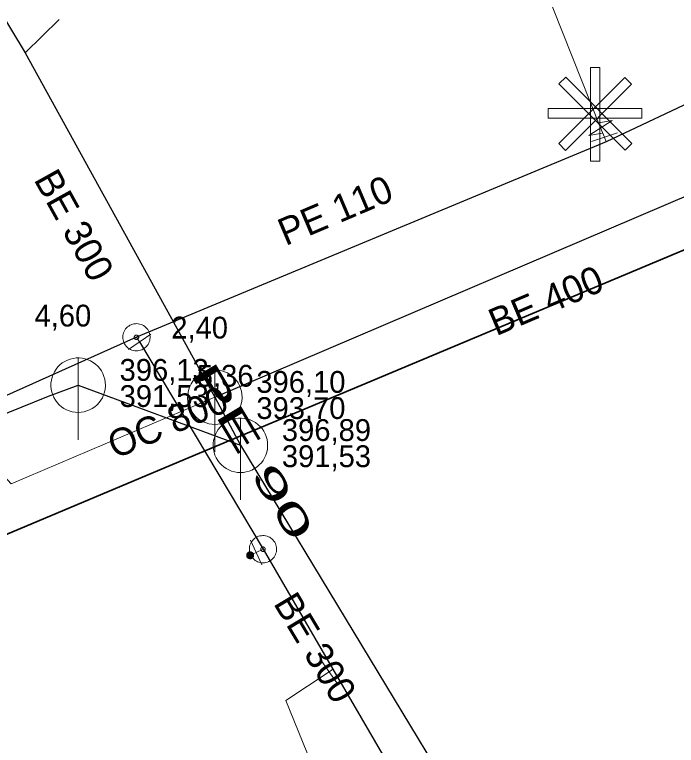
# Model space of a CAD drawing. Extents: x -809028 to -807737, y -990545 to -989489.
# Drawn here: x -808576.58 to -808552.29, y -989992.11 to -989965.3 of the extents above; entities that cross this region are included whole.
import ezdxf

# ---------------------------------------------------------------- set-up
doc = ezdxf.new("R2010")
doc.units = 0
doc.header["$LTSCALE"] = 0.32
for name, color, linetype, lineweight in [('1', 7, 'Continuous', 13), ('11', 7, 'Continuous', 13), ('12', 7, 'Continuous', 13), ('13', 7, 'Continuous', 13), ('14', 7, 'Continuous', 25), ('17', 7, 'Continuous', 25), ('22', 7, 'Continuous', 13), ('34', 7, 'Continuous', 13), ('47', 7, 'Continuous', 13), ('9', 7, 'Continuous', 13)]:
    doc.layers.add(name, color=color, linetype=linetype, lineweight=lineweight)

msp = doc.modelspace()

# ---------------------------------------------------------------- linework, layer by layer
at = {"layer": '11'}
msp.add_line((-808574.951, -989965.476), (-808576.188, -989966.702), dxfattribs=at)
msp.add_lwpolyline([(-808584.044, -989974.464), (-808576.71, -989982.519), (-808569.23, -989979.334)], dxfattribs=at)
at = {"layer": '12'}
for points in [[(-808555.447, -989967.24), (-808555.097, -989967.24), (-808555.097, -989970.675), (-808555.447, -989970.675)], [(-808554.181, -989967.604), (-808553.933, -989967.852), (-808556.362, -989970.281), (-808556.608, -989970.033)], [(-808556.6, -989967.843), (-808556.353, -989967.595), (-808553.924, -989970.024), (-808554.171, -989970.272)], [(-808553.563, -989968.749), (-808553.563, -989969.099), (-808556.998, -989969.099), (-808556.998, -989968.749)]]:
    msp.add_lwpolyline(points, close=True, dxfattribs=at)
at = {"layer": '13'}
for points in [[(-808554.927, -989969.793), (-808555.077, -989969.458), (-808560.651, -989955.405)], [(-808565.037, -989989.409), (-808566.625, -989990.465), (-808565.535, -989993.138), (-808569.495, -989996.061)]]:
    msp.add_lwpolyline(points, dxfattribs=at)
at = {"layer": '14', "lineweight": 13}
for p, q in [((-808554.87, -989969.971), (-808554.927, -989969.793)), ((-808572.108, -989977.136), (-808571.991, -989977.309)), ((-808567.716, -989985.034), (-808567.935, -989985.135)), ((-808567.463, -989984.912), (-808567.716, -989985.034))]:
    msp.add_line(p, q, dxfattribs=at)
at = {"layer": '14'}
msp.add_line((-808574.249, -989978.893), (-808568.292, -989981.1), dxfattribs=at)
for points in [[(-808584.261, -989952.94), (-808577.742, -989964.137), (-808576.188, -989966.702), (-808569.23, -989979.334)], [(-808569.23, -989979.334), (-808549.572, -989970.943), (-808544.651, -989968.803)], [(-808603.873, -989990.789), (-808591.761, -989985.934), (-808575.342, -989979.291), (-808574.249, -989978.893)], [(-808569.23, -989979.334), (-808568.292, -989981.1), (-808559.407, -989995.771), (-808556.033, -990001.675), (-808538.055, -990031.421), (-808535.03, -990036.115), (-808522.248, -990056.603), (-808501.469, -990070.893)]]:
    msp.add_lwpolyline(points, dxfattribs=at)
at = {"layer": '14', "lineweight": 13}
msp.add_lwpolyline([(-808565.037, -989989.409), (-808564.997, -989989.381), (-808564.903, -989989.315)], dxfattribs=at)
at = {"layer": '17'}
msp.add_line((-808571.991, -989977.309), (-808567.463, -989984.912), dxfattribs=at)
for points in [[(-808533.093, -989960.754), (-808533.43, -989961.315), (-808534.199, -989961.752), (-808534.647, -989961.113), (-808551.155, -989968.217), (-808554.87, -989969.971), (-808572.108, -989977.136)], [(-808572.108, -989977.136), (-808579.511, -989980.449), (-808588.848, -989984.113), (-808599.937, -989988.868)], [(-808567.463, -989984.912), (-808564.903, -989989.315), (-808559.226, -989999.059), (-808546.874, -990020.305), (-808545.364, -990022.763), (-808542.872, -990026.881), (-808542.522, -990027.583), (-808541.645, -990028.908), (-808532.624, -990043.916), (-808522.756, -990058.613), (-808516.815, -990065.144), (-808508.914, -990069.898)]]:
    msp.add_lwpolyline(points, dxfattribs=at)
at = {"layer": '17', "lineweight": 35}
msp.add_lwpolyline([(-808620.873, -990007.571), (-808617.482, -990003.458), (-808605.335, -989996.355), (-808589.077, -989989.493), (-808570.179, -989981.543), (-808534.115, -989966.436)], dxfattribs=at)
at = {"layer": '22'}
for p, q in [((-808574.249, -989980.893), (-808574.248, -989977.893)), ((-808569.23, -989981.334), (-808569.229, -989978.334)), ((-808568.292, -989983.1), (-808568.291, -989980.1))]:
    msp.add_line(p, q, dxfattribs=at)
for points in [[(-808573.249, -989978.893), (-808573.254, -989978.784), (-808573.272, -989978.676), (-808573.302, -989978.57), (-808573.342, -989978.469), (-808573.394, -989978.372), (-808573.456, -989978.282), (-808573.528, -989978.199), (-808573.608, -989978.125), (-808573.696, -989978.059), (-808573.79, -989978.004), (-808573.89, -989977.959), (-808573.995, -989977.926), (-808574.102, -989977.904), (-808574.211, -989977.894), (-808574.321, -989977.896), (-808574.429, -989977.91), (-808574.536, -989977.935), (-808574.639, -989977.972), (-808574.737, -989978.021), (-808574.829, -989978.079), (-808574.915, -989978.148), (-808574.992, -989978.225), (-808575.061, -989978.311), (-808575.12, -989978.403), (-808575.168, -989978.501), (-808575.205, -989978.604), (-808575.231, -989978.711), (-808575.245, -989978.819), (-808575.248, -989978.929), (-808575.238, -989979.038), (-808575.217, -989979.145), (-808575.183, -989979.249), (-808575.139, -989979.349), (-808575.084, -989979.444), (-808575.018, -989979.532), (-808574.944, -989979.612), (-808574.861, -989979.684), (-808574.771, -989979.746), (-808574.675, -989979.798), (-808574.573, -989979.839), (-808574.468, -989979.869), (-808574.36, -989979.887), (-808574.25, -989979.893), (-808574.141, -989979.887), (-808574.033, -989979.869), (-808573.928, -989979.84), (-808573.826, -989979.799), (-808573.729, -989979.747), (-808573.639, -989979.685), (-808573.556, -989979.614), (-808573.481, -989979.534), (-808573.416, -989979.446), (-808573.36, -989979.352), (-808573.316, -989979.252), (-808573.282, -989979.148), (-808573.26, -989979.04), (-808573.25, -989978.931)], [(-808568.23, -989979.334), (-808568.235, -989979.225), (-808568.253, -989979.117), (-808568.283, -989979.011), (-808568.323, -989978.91), (-808568.375, -989978.813), (-808568.437, -989978.723), (-808568.509, -989978.64), (-808568.589, -989978.566), (-808568.677, -989978.5), (-808568.771, -989978.445), (-808568.871, -989978.4), (-808568.976, -989978.367), (-808569.083, -989978.345), (-808569.192, -989978.335), (-808569.302, -989978.337), (-808569.41, -989978.351), (-808569.517, -989978.376), (-808569.62, -989978.413), (-808569.718, -989978.462), (-808569.81, -989978.52), (-808569.896, -989978.589), (-808569.973, -989978.666), (-808570.042, -989978.752), (-808570.101, -989978.844), (-808570.149, -989978.942), (-808570.186, -989979.045), (-808570.212, -989979.152), (-808570.226, -989979.26), (-808570.229, -989979.37), (-808570.219, -989979.479), (-808570.198, -989979.586), (-808570.164, -989979.69), (-808570.12, -989979.79), (-808570.065, -989979.885), (-808569.999, -989979.973), (-808569.925, -989980.053), (-808569.842, -989980.125), (-808569.752, -989980.187), (-808569.656, -989980.239), (-808569.554, -989980.28), (-808569.449, -989980.31), (-808569.341, -989980.328), (-808569.231, -989980.334), (-808569.122, -989980.328), (-808569.014, -989980.31), (-808568.909, -989980.281), (-808568.807, -989980.24), (-808568.71, -989980.188), (-808568.62, -989980.126), (-808568.537, -989980.055), (-808568.462, -989979.975), (-808568.397, -989979.887), (-808568.341, -989979.793), (-808568.297, -989979.693), (-808568.263, -989979.589), (-808568.241, -989979.481), (-808568.231, -989979.372)], [(-808567.292, -989981.1), (-808567.297, -989980.991), (-808567.315, -989980.883), (-808567.345, -989980.777), (-808567.385, -989980.676), (-808567.437, -989980.579), (-808567.499, -989980.489), (-808567.571, -989980.406), (-808567.651, -989980.332), (-808567.739, -989980.266), (-808567.833, -989980.211), (-808567.933, -989980.166), (-808568.038, -989980.133), (-808568.145, -989980.111), (-808568.254, -989980.101), (-808568.364, -989980.103), (-808568.472, -989980.117), (-808568.579, -989980.142), (-808568.682, -989980.179), (-808568.78, -989980.228), (-808568.872, -989980.286), (-808568.958, -989980.355), (-808569.035, -989980.432), (-808569.104, -989980.518), (-808569.163, -989980.61), (-808569.211, -989980.708), (-808569.248, -989980.811), (-808569.274, -989980.918), (-808569.288, -989981.026), (-808569.291, -989981.136), (-808569.281, -989981.245), (-808569.26, -989981.352), (-808569.226, -989981.456), (-808569.182, -989981.556), (-808569.127, -989981.651), (-808569.061, -989981.739), (-808568.987, -989981.819), (-808568.904, -989981.891), (-808568.814, -989981.953), (-808568.718, -989982.005), (-808568.616, -989982.046), (-808568.511, -989982.076), (-808568.403, -989982.094), (-808568.293, -989982.1), (-808568.184, -989982.094), (-808568.076, -989982.076), (-808567.971, -989982.047), (-808567.869, -989982.006), (-808567.772, -989981.954), (-808567.682, -989981.892), (-808567.599, -989981.821), (-808567.524, -989981.741), (-808567.459, -989981.653), (-808567.403, -989981.559), (-808567.359, -989981.459), (-808567.325, -989981.355), (-808567.303, -989981.247), (-808567.293, -989981.138)]]:
    msp.add_lwpolyline(points, close=True, dxfattribs=at)
at = {"layer": '34'}
for p, q in [((-808554.452, -989969.636), (-808555.402, -989969.948)), ((-808571.577, -989977.027), (-808572.404, -989977.589)), ((-808567.926, -989984.58), (-808567.506, -989985.488)), ((-808565.322, -989988.998), (-808564.752, -989989.819))]:
    msp.add_line(p, q, dxfattribs=at)
at = {"layer": '47'}
msp.add_line((-808554.648, -989969.182), (-808555.151, -989969.271), dxfattribs=at)
msp.add_lwpolyline([(-808554.648, -989969.182), (-808555.505, -989969.733), (-808555.002, -989969.644)], dxfattribs=at)
for points in [[(-808571.646, -989976.944), (-808571.669, -989976.897), (-808571.696, -989976.852), (-808571.728, -989976.811), (-808571.763, -989976.773), (-808571.804, -989976.738), (-808571.847, -989976.709), (-808571.893, -989976.685), (-808571.941, -989976.665), (-808571.991, -989976.65), (-808572.043, -989976.64), (-808572.095, -989976.636), (-808572.148, -989976.638), (-808572.199, -989976.644), (-808572.25, -989976.657), (-808572.299, -989976.674), (-808572.346, -989976.697), (-808572.391, -989976.724), (-808572.433, -989976.756), (-808572.47, -989976.791), (-808572.505, -989976.832), (-808572.534, -989976.875), (-808572.559, -989976.922), (-808572.579, -989976.97), (-808572.594, -989977.019), (-808572.603, -989977.071), (-808572.607, -989977.123), (-808572.606, -989977.176), (-808572.599, -989977.227), (-808572.586, -989977.278), (-808572.569, -989977.327), (-808572.546, -989977.374), (-808572.519, -989977.419), (-808572.488, -989977.461), (-808572.452, -989977.498), (-808572.411, -989977.533), (-808572.369, -989977.562), (-808572.322, -989977.588), (-808572.274, -989977.608), (-808572.224, -989977.622), (-808572.172, -989977.631), (-808572.12, -989977.635), (-808572.068, -989977.635), (-808572.016, -989977.627), (-808571.965, -989977.614), (-808571.916, -989977.597), (-808571.869, -989977.574), (-808571.824, -989977.547), (-808571.783, -989977.516), (-808571.745, -989977.48), (-808571.71, -989977.439), (-808571.681, -989977.397), (-808571.656, -989977.351), (-808571.636, -989977.302), (-808571.622, -989977.252), (-808571.612, -989977.2), (-808571.608, -989977.148), (-808571.609, -989977.096), (-808571.616, -989977.044), (-808571.629, -989976.993)], [(-808572.032, -989977.104), (-808572.035, -989977.096), (-808572.04, -989977.089), (-808572.045, -989977.082), (-808572.051, -989977.076), (-808572.058, -989977.07), (-808572.065, -989977.066), (-808572.072, -989977.061), (-808572.08, -989977.058), (-808572.089, -989977.056), (-808572.097, -989977.054), (-808572.106, -989977.054), (-808572.114, -989977.054), (-808572.123, -989977.055), (-808572.131, -989977.056), (-808572.139, -989977.06), (-808572.147, -989977.063), (-808572.154, -989977.068), (-808572.161, -989977.073), (-808572.167, -989977.079), (-808572.173, -989977.086), (-808572.177, -989977.093), (-808572.182, -989977.1), (-808572.185, -989977.108), (-808572.188, -989977.117), (-808572.189, -989977.125), (-808572.189, -989977.134), (-808572.189, -989977.142), (-808572.188, -989977.151), (-808572.187, -989977.159), (-808572.183, -989977.167), (-808572.18, -989977.175), (-808572.175, -989977.182), (-808572.17, -989977.189), (-808572.164, -989977.195), (-808572.157, -989977.201), (-808572.151, -989977.206), (-808572.143, -989977.21), (-808572.135, -989977.213), (-808572.126, -989977.216), (-808572.118, -989977.217), (-808572.109, -989977.217), (-808572.101, -989977.217), (-808572.092, -989977.216), (-808572.084, -989977.215), (-808572.076, -989977.211), (-808572.068, -989977.208), (-808572.061, -989977.203), (-808572.054, -989977.198), (-808572.048, -989977.192), (-808572.042, -989977.185), (-808572.037, -989977.179), (-808572.033, -989977.171), (-808572.03, -989977.163), (-808572.028, -989977.154), (-808572.026, -989977.146), (-808572.026, -989977.137), (-808572.026, -989977.129), (-808572.027, -989977.12), (-808572.028, -989977.112)], [(-808567.207, -989985.341), (-808567.164, -989985.312), (-808567.123, -989985.278), (-808567.087, -989985.241), (-808567.054, -989985.2), (-808567.026, -989985.156), (-808567.003, -989985.108), (-808566.986, -989985.059), (-808566.973, -989985.009), (-808566.965, -989984.957), (-808566.963, -989984.905), (-808566.966, -989984.852), (-808566.976, -989984.801), (-808566.989, -989984.751), (-808567.009, -989984.702), (-808567.033, -989984.656), (-808567.062, -989984.613), (-808567.096, -989984.572), (-808567.134, -989984.535), (-808567.174, -989984.503), (-808567.218, -989984.475), (-808567.266, -989984.452), (-808567.315, -989984.434), (-808567.366, -989984.421), (-808567.417, -989984.413), (-808567.469, -989984.412), (-808567.522, -989984.415), (-808567.574, -989984.424), (-808567.623, -989984.438), (-808567.672, -989984.458), (-808567.718, -989984.482), (-808567.761, -989984.511), (-808567.802, -989984.545), (-808567.839, -989984.582), (-808567.871, -989984.623), (-808567.899, -989984.667), (-808567.922, -989984.714), (-808567.941, -989984.763), (-808567.954, -989984.814), (-808567.961, -989984.866), (-808567.962, -989984.918), (-808567.959, -989984.971), (-808567.951, -989985.022), (-808567.936, -989985.072), (-808567.916, -989985.121), (-808567.892, -989985.167), (-808567.863, -989985.21), (-808567.829, -989985.251), (-808567.793, -989985.287), (-808567.751, -989985.32), (-808567.707, -989985.348), (-808567.66, -989985.371), (-808567.611, -989985.389), (-808567.56, -989985.402), (-808567.508, -989985.409), (-808567.456, -989985.411), (-808567.403, -989985.408), (-808567.353, -989985.399), (-808567.302, -989985.385), (-808567.253, -989985.365)], [(-808567.421, -989984.982), (-808567.413, -989984.977), (-808567.407, -989984.972), (-808567.401, -989984.966), (-808567.396, -989984.959), (-808567.391, -989984.952), (-808567.387, -989984.944), (-808567.384, -989984.936), (-808567.382, -989984.928), (-808567.381, -989984.919), (-808567.381, -989984.91), (-808567.381, -989984.901), (-808567.383, -989984.893), (-808567.385, -989984.885), (-808567.387, -989984.877), (-808567.392, -989984.87), (-808567.397, -989984.862), (-808567.402, -989984.856), (-808567.408, -989984.85), (-808567.415, -989984.845), (-808567.422, -989984.84), (-808567.43, -989984.836), (-808567.438, -989984.833), (-808567.446, -989984.831), (-808567.456, -989984.829), (-808567.464, -989984.83), (-808567.473, -989984.83), (-808567.481, -989984.832), (-808567.489, -989984.834), (-808567.497, -989984.836), (-808567.504, -989984.841), (-808567.512, -989984.846), (-808567.518, -989984.851), (-808567.524, -989984.857), (-808567.529, -989984.864), (-808567.534, -989984.871), (-808567.538, -989984.878), (-808567.541, -989984.887), (-808567.543, -989984.895), (-808567.545, -989984.905), (-808567.544, -989984.913), (-808567.544, -989984.922), (-808567.542, -989984.93), (-808567.54, -989984.938), (-808567.538, -989984.946), (-808567.533, -989984.953), (-808567.528, -989984.961), (-808567.523, -989984.967), (-808567.517, -989984.973), (-808567.51, -989984.978), (-808567.503, -989984.983), (-808567.496, -989984.987), (-808567.487, -989984.99), (-808567.479, -989984.992), (-808567.47, -989984.993), (-808567.461, -989984.993), (-808567.452, -989984.993), (-808567.444, -989984.991), (-808567.436, -989984.989), (-808567.428, -989984.987)]]:
    msp.add_lwpolyline(points, close=True, dxfattribs=at)
at = {"layer": '9'}
for points in [[(-808568.061, -989985.135), (-808568.061, -989985.148), (-808568.059, -989985.161), (-808568.056, -989985.174), (-808568.051, -989985.186), (-808568.045, -989985.198), (-808568.038, -989985.209), (-808568.03, -989985.219), (-808568.02, -989985.229), (-808568.01, -989985.237), (-808567.999, -989985.244), (-808567.987, -989985.25), (-808567.975, -989985.255), (-808567.962, -989985.258), (-808567.949, -989985.26), (-808567.936, -989985.262), (-808567.923, -989985.261), (-808567.91, -989985.259), (-808567.897, -989985.256), (-808567.885, -989985.251), (-808567.873, -989985.245), (-808567.862, -989985.238), (-808567.852, -989985.23), (-808567.842, -989985.22), (-808567.834, -989985.21), (-808567.827, -989985.199), (-808567.821, -989985.187), (-808567.816, -989985.175), (-808567.813, -989985.162), (-808567.811, -989985.149), (-808567.809, -989985.136), (-808567.81, -989985.123), (-808567.812, -989985.11), (-808567.815, -989985.097), (-808567.82, -989985.085), (-808567.826, -989985.073), (-808567.833, -989985.062), (-808567.841, -989985.052), (-808567.851, -989985.042), (-808567.861, -989985.034), (-808567.872, -989985.027), (-808567.884, -989985.021), (-808567.896, -989985.016), (-808567.909, -989985.013), (-808567.922, -989985.011), (-808567.935, -989985.01), (-808567.948, -989985.01), (-808567.961, -989985.012), (-808567.974, -989985.015), (-808567.986, -989985.02), (-808567.998, -989985.026), (-808568.009, -989985.033), (-808568.019, -989985.041), (-808568.029, -989985.051), (-808568.037, -989985.061), (-808568.044, -989985.072), (-808568.05, -989985.084), (-808568.055, -989985.096), (-808568.058, -989985.109), (-808568.06, -989985.122)], [(-808568.041, -989985.135), (-808568.042, -989985.146), (-808568.04, -989985.157), (-808568.037, -989985.168), (-808568.033, -989985.178), (-808568.028, -989985.188), (-808568.022, -989985.197), (-808568.015, -989985.206), (-808568.007, -989985.214), (-808567.998, -989985.221), (-808567.989, -989985.227), (-808567.979, -989985.232), (-808567.969, -989985.236), (-808567.958, -989985.239), (-808567.947, -989985.242), (-808567.936, -989985.242), (-808567.925, -989985.242), (-808567.914, -989985.24), (-808567.903, -989985.237), (-808567.893, -989985.233), (-808567.883, -989985.228), (-808567.874, -989985.222), (-808567.865, -989985.215), (-808567.857, -989985.207), (-808567.85, -989985.198), (-808567.844, -989985.189), (-808567.839, -989985.179), (-808567.835, -989985.169), (-808567.832, -989985.158), (-808567.83, -989985.147), (-808567.829, -989985.136), (-808567.829, -989985.125), (-808567.831, -989985.114), (-808567.834, -989985.103), (-808567.838, -989985.093), (-808567.843, -989985.083), (-808567.849, -989985.074), (-808567.856, -989985.065), (-808567.864, -989985.057), (-808567.873, -989985.05), (-808567.882, -989985.044), (-808567.892, -989985.039), (-808567.902, -989985.035), (-808567.913, -989985.032), (-808567.924, -989985.03), (-808567.935, -989985.03), (-808567.946, -989985.029), (-808567.957, -989985.031), (-808567.968, -989985.034), (-808567.978, -989985.038), (-808567.988, -989985.043), (-808567.997, -989985.049), (-808568.006, -989985.056), (-808568.014, -989985.064), (-808568.021, -989985.073), (-808568.027, -989985.082), (-808568.032, -989985.092), (-808568.036, -989985.102), (-808568.039, -989985.113), (-808568.041, -989985.124)], [(-808568.022, -989985.135), (-808568.022, -989985.144), (-808568.021, -989985.153), (-808568.018, -989985.162), (-808568.015, -989985.17), (-808568.011, -989985.178), (-808568.006, -989985.186), (-808568, -989985.193), (-808567.994, -989985.199), (-808567.987, -989985.205), (-808567.979, -989985.21), (-808567.971, -989985.214), (-808567.963, -989985.217), (-808567.954, -989985.22), (-808567.945, -989985.221), (-808567.936, -989985.223), (-808567.927, -989985.222), (-808567.918, -989985.221), (-808567.909, -989985.218), (-808567.901, -989985.215), (-808567.893, -989985.211), (-808567.885, -989985.206), (-808567.878, -989985.2), (-808567.872, -989985.194), (-808567.866, -989985.187), (-808567.861, -989985.179), (-808567.857, -989985.171), (-808567.854, -989985.163), (-808567.851, -989985.154), (-808567.85, -989985.145), (-808567.848, -989985.136), (-808567.849, -989985.127), (-808567.85, -989985.118), (-808567.853, -989985.109), (-808567.856, -989985.101), (-808567.86, -989985.093), (-808567.865, -989985.085), (-808567.871, -989985.078), (-808567.877, -989985.072), (-808567.884, -989985.066), (-808567.892, -989985.061), (-808567.9, -989985.057), (-808567.908, -989985.054), (-808567.917, -989985.051), (-808567.926, -989985.05), (-808567.935, -989985.049), (-808567.944, -989985.049), (-808567.953, -989985.05), (-808567.962, -989985.053), (-808567.97, -989985.056), (-808567.978, -989985.06), (-808567.986, -989985.065), (-808567.993, -989985.071), (-808567.999, -989985.077), (-808568.005, -989985.084), (-808568.01, -989985.092), (-808568.014, -989985.1), (-808568.017, -989985.108), (-808568.02, -989985.117), (-808568.021, -989985.126)], [(-808568.002, -989985.135), (-808568.002, -989985.142), (-808568.001, -989985.149), (-808568, -989985.156), (-808567.997, -989985.162), (-808567.994, -989985.168), (-808567.99, -989985.174), (-808567.986, -989985.18), (-808567.981, -989985.185), (-808567.975, -989985.189), (-808567.969, -989985.193), (-808567.963, -989985.196), (-808567.957, -989985.199), (-808567.95, -989985.2), (-808567.943, -989985.203), (-808567.936, -989985.203), (-808567.929, -989985.203), (-808567.922, -989985.201), (-808567.915, -989985.2), (-808567.909, -989985.197), (-808567.902, -989985.194), (-808567.897, -989985.19), (-808567.891, -989985.186), (-808567.886, -989985.181), (-808567.882, -989985.175), (-808567.878, -989985.169), (-808567.875, -989985.163), (-808567.872, -989985.157), (-808567.87, -989985.15), (-808567.869, -989985.143), (-808567.868, -989985.136), (-808567.868, -989985.129), (-808567.869, -989985.122), (-808567.871, -989985.115), (-808567.874, -989985.109), (-808567.877, -989985.102), (-808567.881, -989985.097), (-808567.885, -989985.091), (-808567.89, -989985.086), (-808567.896, -989985.082), (-808567.901, -989985.078), (-808567.908, -989985.075), (-808567.914, -989985.072), (-808567.921, -989985.07), (-808567.928, -989985.069), (-808567.935, -989985.069), (-808567.942, -989985.069), (-808567.949, -989985.069), (-808567.956, -989985.071), (-808567.962, -989985.074), (-808567.968, -989985.077), (-808567.974, -989985.081), (-808567.98, -989985.085), (-808567.985, -989985.09), (-808567.989, -989985.096), (-808567.993, -989985.101), (-808567.996, -989985.108), (-808567.999, -989985.114), (-808568, -989985.121), (-808568.002, -989985.128)], [(-808567.982, -989985.135), (-808567.982, -989985.14), (-808567.982, -989985.145), (-808567.981, -989985.15), (-808567.979, -989985.154), (-808567.977, -989985.159), (-808567.974, -989985.163), (-808567.971, -989985.166), (-808567.967, -989985.17), (-808567.964, -989985.173), (-808567.96, -989985.176), (-808567.955, -989985.178), (-808567.951, -989985.18), (-808567.946, -989985.181), (-808567.941, -989985.183), (-808567.936, -989985.183), (-808567.931, -989985.183), (-808567.926, -989985.182), (-808567.921, -989985.181), (-808567.917, -989985.179), (-808567.912, -989985.177), (-808567.908, -989985.174), (-808567.904, -989985.171), (-808567.901, -989985.167), (-808567.898, -989985.164), (-808567.895, -989985.16), (-808567.893, -989985.155), (-808567.891, -989985.151), (-808567.89, -989985.146), (-808567.889, -989985.141), (-808567.888, -989985.136), (-808567.888, -989985.131), (-808567.889, -989985.126), (-808567.89, -989985.121), (-808567.892, -989985.117), (-808567.894, -989985.112), (-808567.897, -989985.108), (-808567.9, -989985.104), (-808567.903, -989985.101), (-808567.907, -989985.098), (-808567.911, -989985.095), (-808567.916, -989985.093), (-808567.92, -989985.091), (-808567.925, -989985.09), (-808567.93, -989985.089), (-808567.935, -989985.089), (-808567.94, -989985.089), (-808567.945, -989985.09), (-808567.95, -989985.09), (-808567.954, -989985.092), (-808567.959, -989985.094), (-808567.963, -989985.097), (-808567.966, -989985.1), (-808567.97, -989985.103), (-808567.973, -989985.107), (-808567.976, -989985.111), (-808567.978, -989985.116), (-808567.98, -989985.12), (-808567.981, -989985.125), (-808567.982, -989985.13)], [(-808567.962, -989985.135), (-808567.962, -989985.138), (-808567.963, -989985.141), (-808567.962, -989985.143), (-808567.961, -989985.146), (-808567.96, -989985.149), (-808567.958, -989985.151), (-808567.956, -989985.153), (-808567.954, -989985.155), (-808567.952, -989985.157), (-808567.95, -989985.159), (-808567.947, -989985.161), (-808567.944, -989985.162), (-808567.942, -989985.162), (-808567.939, -989985.163), (-808567.936, -989985.163), (-808567.933, -989985.163), (-808567.93, -989985.163), (-808567.927, -989985.162), (-808567.925, -989985.161), (-808567.922, -989985.16), (-808567.92, -989985.158), (-808567.917, -989985.156), (-808567.915, -989985.154), (-808567.914, -989985.152), (-808567.912, -989985.15), (-808567.911, -989985.147), (-808567.909, -989985.144), (-808567.909, -989985.142), (-808567.908, -989985.139), (-808567.907, -989985.136), (-808567.908, -989985.133), (-808567.908, -989985.13), (-808567.909, -989985.127), (-808567.91, -989985.125), (-808567.911, -989985.122), (-808567.913, -989985.12), (-808567.914, -989985.117), (-808567.916, -989985.115), (-808567.919, -989985.114), (-808567.921, -989985.112), (-808567.924, -989985.111), (-808567.926, -989985.11), (-808567.929, -989985.109), (-808567.932, -989985.109), (-808567.935, -989985.108), (-808567.938, -989985.109), (-808567.941, -989985.108), (-808567.943, -989985.11), (-808567.946, -989985.11), (-808567.949, -989985.111), (-808567.951, -989985.113), (-808567.953, -989985.114), (-808567.955, -989985.116), (-808567.957, -989985.119), (-808567.959, -989985.121), (-808567.96, -989985.124), (-808567.961, -989985.126), (-808567.962, -989985.129), (-808567.962, -989985.132)], [(-808567.943, -989985.135), (-808567.943, -989985.137), (-808567.943, -989985.137), (-808567.942, -989985.137), (-808567.942, -989985.139), (-808567.943, -989985.14), (-808567.941, -989985.14), (-808567.941, -989985.14), (-808567.941, -989985.142), (-808567.941, -989985.142), (-808567.94, -989985.143), (-808567.938, -989985.143), (-808567.938, -989985.143), (-808567.938, -989985.144), (-808567.936, -989985.144), (-808567.936, -989985.144), (-808567.935, -989985.144), (-808567.934, -989985.144), (-808567.934, -989985.143), (-808567.933, -989985.143), (-808567.931, -989985.143), (-808567.931, -989985.142), (-808567.931, -989985.142), (-808567.93, -989985.141), (-808567.93, -989985.141), (-808567.928, -989985.14), (-808567.928, -989985.139), (-808567.927, -989985.138), (-808567.927, -989985.138), (-808567.927, -989985.137), (-808567.927, -989985.136), (-808567.927, -989985.135), (-808567.927, -989985.134), (-808567.927, -989985.134), (-808567.928, -989985.133), (-808567.928, -989985.132), (-808567.929, -989985.131), (-808567.929, -989985.131), (-808567.93, -989985.13), (-808567.93, -989985.13), (-808567.931, -989985.129), (-808567.932, -989985.129), (-808567.933, -989985.128), (-808567.933, -989985.128), (-808567.934, -989985.128), (-808567.935, -989985.128), (-808567.936, -989985.128), (-808567.937, -989985.128), (-808567.937, -989985.128), (-808567.938, -989985.129), (-808567.939, -989985.128), (-808567.94, -989985.13), (-808567.94, -989985.13), (-808567.941, -989985.13), (-808567.941, -989985.13), (-808567.942, -989985.132), (-808567.942, -989985.133), (-808567.942, -989985.134), (-808567.943, -989985.134), (-808567.943, -989985.135)]]:
    msp.add_lwpolyline(points, close=True, dxfattribs=at)

# ---------------------------------------------------------------- texts
at = {"layer": '1'}
for s, rotation, p in [('BE 300', 299, (-808575.895, -989971.347)), ('PE 110', 23, (-808566.637, -989973.795)), ('BE 400', 23, (-808558.904, -989977.102)), ('OC 800', 23, (-808572.887, -989981.611)), ('BE 300', 301, (-808567.101, -989986.898))]:
    msp.add_text(s, height=1, rotation=rotation, dxfattribs=at).set_placement(p)
for s, p in [('4,60', (-808575.849, -989976.741)), ('2,40', (-808570.83, -989977.182)), ('5,36', (-808569.892, -989978.948))]:
    msp.add_text(s, height=0.8, dxfattribs=at).set_placement(p)
at = {"layer": '1', "width": 2}
msp.add_text('PE 90 ', height=1, rotation=301, dxfattribs=at).set_placement((-808570.159, -989978.457))
at = {"layer": '14'}
for s, p in [('396,13', (-808572.727, -989978.733)), ('396,10', (-808567.708, -989979.174)), ('391,53', (-808572.727, -989979.693)), ('393,70', (-808567.708, -989980.134)), ('396,89', (-808566.77, -989980.94)), ('391,53', (-808566.77, -989981.9))]:
    msp.add_text(s, height=0.8, dxfattribs=at).set_placement(p)

doc.saveas('drawing.dxf')
